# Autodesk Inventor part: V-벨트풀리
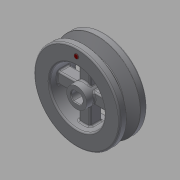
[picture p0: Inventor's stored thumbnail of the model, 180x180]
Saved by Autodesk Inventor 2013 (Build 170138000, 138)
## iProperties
Created: 2018-01
Part Number: V-벨트풀리
Material: 스테인리스강
Document SubType Name: Modeling
Designer: mduedu
Density: 1 g/cm^3
Author: mduedu
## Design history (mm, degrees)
sketch "스케치1"
  geometry: C1 r 30 at (0, 0); 1 further point
  constraints: 1 centre point, 1 coincident
  dimensions: "d0" = 60 diameter of C1
extrude "돌출1" new body sketch "스케치1" stored distance "d1" = 19; taper "d2" = 0 deg
sketch "스케치2"
  geometry: L1 (30, -9.5)-(-30, -9.5) reference; L2 (-30, -9.5)-(-30, 9.5) reference; L3 (-30, 9.5)-(30, 9.5) reference; L4 (30, 9.5)-(30, -9.5) reference; L5 (-30, 0)-(30, 0); L6 (30, 4.825)-(21, 2.074); L7 (21, 2.074)-(21, -2.074); L8 (21, -2.074)-(30, -4.825); L9 (30, -4.825)-(30, 4.825); L10 (27.3, 9.5)-(27.3, -9.5); L11 (0, -13.3)-(0, 13.3) reference; 4 further points
  constraints: 12 end point, 9 point on line, 3 midpoint, 2 perpendicular, 1 collinear, 1 symmetric about line
  dimensions: "d3" = 34 deg angle of L8 L6; "d4" = 2.7 distance between parallel lines of L10 L4; "d5" = 6.3 distance between parallel lines of L7 L10; "d6" = 8 distance of point (27.3, -4) point (27.3, 4)
revolve "회전1" sketch "스케치2" stored, may be unused: angle "d7" = 90 deg
fillet "모깎기1" dims "d8" = 0.2
fillet "모깎기2" dims "d9" = 0.5
fillet "모깎기3" dims "d10" = 1
sketch "스케치3"
  geometry: C1 r 19 at (0, 0); 1 further point
  constraints: 1 centre point, 1 coincident
  dimensions: "d11" = 38 diameter of C1
extrude "돌출2" cut sketch "스케치3" stored distance "d12" = 19; taper "d13" = 0 deg
sketch "스케치4"
  geometry: C1 r 7 at (0, 0); 1 further point
  constraints: 1 centre point, 1 coincident
  dimensions: "d14" = 14 diameter of C1
extrude "돌출3" join sketch "스케치4" stored distance "d15" = 19; taper "d16" = 0 deg
sketch "스케치5"
  geometry: L1 (0, 7)-(0, 19); L2 (4, 5.745)-(4, 18.574); L3 (-4, 5.745)-(-4, 18.574); C1 r 21 at (0, 0) reference; A1 r 19 centre (0, 0) between (0, 19) and (-4, 18.574) reference; A2 r 7 centre (0, 0) between (0, 7) and (-4, 5.745) reference; 1 further point
  constraints: 6 end point, 6 point on circle, 2 parallel, 1 point on line, 1 vertical, 1 other
  dimensions: "d17" = 8 distance between parallel lines of L2 L3
extrude "돌출4" join sketch "스케치5" stored distance "d18" = 8; taper "d19" = 0 deg
fillet "모깎기4" dims "d20" = 1
fillet "모깎기5" dims "d24" = 1
fillet "모깎기6" dims "d25" = 1
hole "구멍1" diameter "d28" = 8; stored, may be unused: countersink angle "d32" = 90 deg, drill point angle "d34" = 118 deg; dims "d26" = 10, "d27" = 10, "d29" = 6, "d30" = 4, "d31" = 2, "d33" = 8
sketch "스케치6"
  geometry: L1 (-2.332, -3.25)-(2.332, -3.25); L2 (2.332, 3.25)-(-2.332, 3.25); L3 (-2.332, -3.25)-(2.332, 3.25); L4 (2.332, -3.25)-(-2.332, 3.25); A1 r 4 centre (0, 0) between (2.332, 3.25) and (-2.332, 3.25) reference; A2 r 4 centre (0, 0) between (2.332, 3.25) and (-2.332, 3.25); A3 r 4 centre (0, 0) between (-2.332, -3.25) and (2.332, -3.25); 1 further point
  constraints: 8 end point, 7 point on circle, 2 centre point, 2 coincident, 2 midpoint, 1 horizontal, 1 parallel
  dimensions: "d35" = 6.5 distance of L1.end L2.start
extrude "돌출5" join sketch "스케치6" stored distance "d37" = 8; taper "d38" = 0 deg
chamfer "모따기1" distance "d39" = 0.5; stored, may be unused: second distance "d40" = 2, angle "d41" = 45 deg
chamfer "모따기2" distance "d42" = 0.5; stored, may be unused: second distance "d43" = 2, angle "d44" = 45 deg
sketch "스케치7" dims "d45" = 50
  geometry: C1 r 1.5 at (0, 25); 2 further points
  constraints: 2 vertical alignment, 1 centre point, 1 coincident, 2 other
  dimensions: "d46" = 3 diameter of C1
extrude "돌출6" join sketch "스케치7" distance "d47" = 0.5; taper "d48" = 0 deg
fillet "모깎기7" dims "d49" = 0.1
node "솔리드1"
pattern_circular "원형 패턴1" dims angle "d22" = 360 deg
node "절단 모서리 투영1"
node "절단 모서리 투영2"
